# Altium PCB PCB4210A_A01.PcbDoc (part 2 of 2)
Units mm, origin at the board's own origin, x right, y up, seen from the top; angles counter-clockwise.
Board outline 30 x 45 mm, 4 copper layers (Top Layer, Signal Layer 2, Signal Layer 3, Bottom Layer), stack 1.6 mm thick; 78 components, 78 nets, 297 pads, 463 vias.
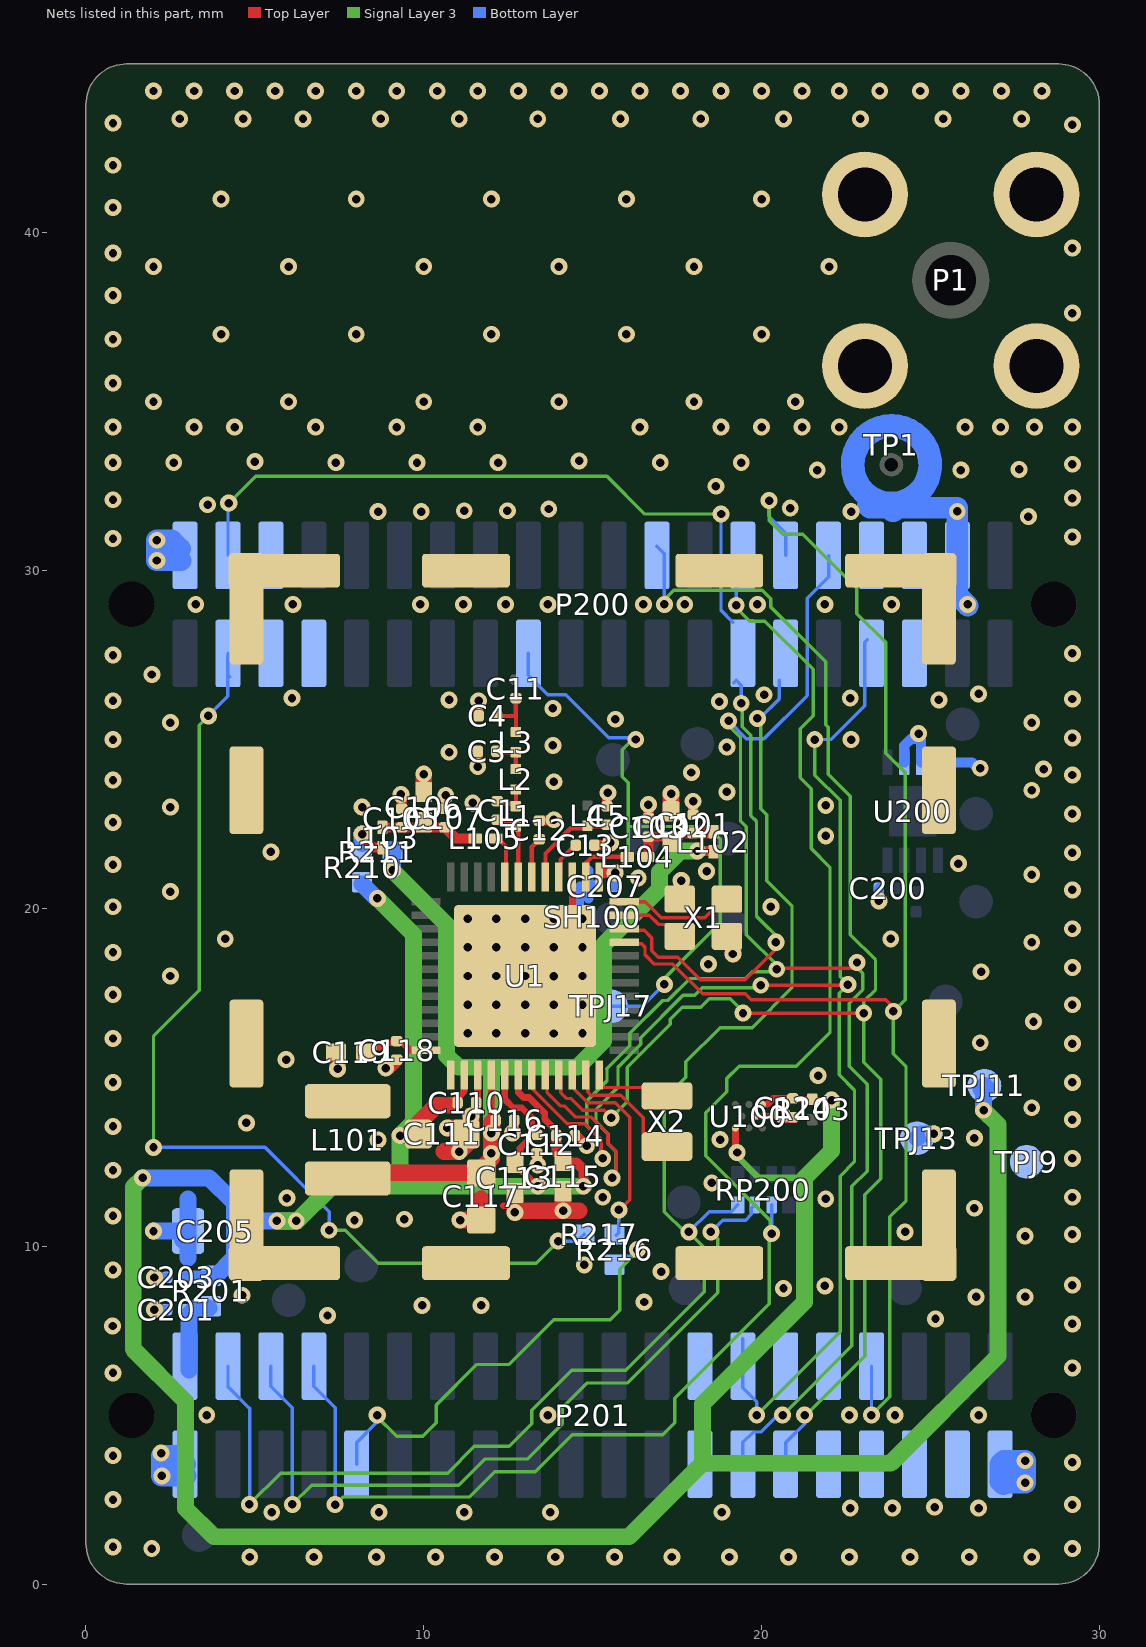
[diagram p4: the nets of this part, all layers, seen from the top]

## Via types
v1: diameter 0.5, hole 0.25, Top Layer to Bottom Layer, tented both sides, 383 vias
v2: diameter 0.508, hole 0.25, Top Layer to Bottom Layer, tented both sides, 80 vias

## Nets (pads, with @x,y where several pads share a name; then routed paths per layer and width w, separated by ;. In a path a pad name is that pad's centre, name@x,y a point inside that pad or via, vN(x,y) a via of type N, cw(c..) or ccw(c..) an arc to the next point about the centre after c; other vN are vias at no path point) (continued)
EFR32_PC8: P200.30 P201.34 U1.9 | length 42.1
  Top Layer w0.1: U1.9@15.935,19 15.985,18.95 16.45,18.95 16.55,18.85 16.55,18.633 16.828,18.355 17.376,18.355 18.255,17.476 19.524,17.476 19.7,17.3 23.677,17.3 23.901,17.076 v2(23.901,16.951)
  Signal Layer 3 w0.1: v2(20.225,32.075) 20.225,31.475 20.625,31.075 21.225,31.075 22.822,29.478 22.822,28.728 23.675,27.875 23.675,24.6 24.25,24.025 24.25,17.3 v2(23.901,16.951) 23.901,15.699 24.274,15.326 24.277,11.352 23.8,10.875 23.8,5.55 v2(23.25,5)
  Bottom Layer w0.1: v2(20.225,32.075) 20.225,31.6 20.715,31.11 P200.30@20.715,30.45 ; v2@23.25,5.05 23.255,5.055 P201.34@23.255,6.45
EFR32_PC9: P200.4 P200.27 U1.10 | length 35.2
  Top Layer w0.1: U1.10@15.935,19.4 15.985,19.35 16.525,19.35 16.75,19.125 16.75,18.75 16.945,18.555 17.52,18.555 18.186,17.889 19.514,17.889 v2@20.488,18.862
  Signal Layer 3 w0.1: v2(4.225,32.002) 4.248,32.002 4.238,32.012 5.025,32.8 15.425,32.8 16.548,31.677 v1(18.801,31.677) ; v2@20.626,18.999 19.85,19.775 19.85,22.575 19.675,22.75 19.675,25.125 19.425,25.375 ; 19.425,25.375 19.425,26.05 19.425,25.375
  Bottom Layer w0.1: P200.4@4.205,30.45 4.205,31.93 v2@4.25,31.975 ; v1(18.801,31.677) 18.724,31.6 18.8,31.524 18.8,28.825 P200.27@19.15,28.475 ; P200.27@19.175,26.675 19.25,26.75 19.4,26.6 v1(19.4,26.075)
  other v2: 20.425,19
EFR32_PD0: U1.48 X2.1 | length 2
  Top Layer w0.1: U1.48@15.2,14.725 15.225,14.7 17.075,14.7 X2.1@17.15,14.775
EFR32_PD1: U1.47 X2.2 | length 3.7
  Top Layer w0.1: U1.47@14.8,15.065 14.85,15.015 14.85,14.575 14.95,14.475 15.825,14.475 16.5,13.8 16.5,13.275 X2.2@17.15,13.275
EFR32_PD2: R216.1 R217.1 U1.46 | length 6.1
  Top Layer w0.1: U1.46@14.4,15.065 14.4,14.708 14.858,14.25 15.675,14.25 16.1,13.825 16.1,11.375 v1@15.8,11.075
  Signal Layer 3 w0.1: v1@15.775,11.1 v1@15.8,11.075
  Bottom Layer w0.1: R216.1@15.7,10.325 15.775,10.4 v1(15.775,11.075)
EFR32_PD3: P200.24 P201.29 U1.45 | length 46.4
  Top Layer w0.1: U1.45@14,15.065 14.05,15.015 14.05,14.55 14.225,14.375 14.35,14.375 14.7,14.025 15.35,14.025 15.55,13.825 v1(15.55,13.8) ; v1(19.45,16.9) 19.45,17.002 19.501,16.951 19.526,16.926 19.576,16.976 19.627,16.925 19.652,16.9 v1(23.025,16.9)
  Signal Layer 3 w0.1: v1(15.55,13.8) 16.025,14.275 16.025,15.292 17.3,16.567 17.3,16.725 17.65,17.075 18.2,17.075 18.45,17.325 19.075,17.325 19.45,16.95 v1(19.45,16.9) ; v1(17.125,29) 16.975,29 17.4,29.425 20.017,29.425 20.276,29.166 20.276,28.924 21.9,27.3 21.9,25.442 21.975,25.367 21.975,23.975 22.625,23.325 22.625,19.225 23.375,18.475 23.375,17.6 23.025,17.25 v1(23.025,16.9) 23.025,15.45 23.525,14.95 23.525,12 23.05,11.525 23.05,6.742 21.308,5 v1(21.275,5)
  Bottom Layer w0.1: P200.24@16.9,30.725 17.125,30.5 v1(17.125,29) ; P201.29@20.715,3.55 20.715,4.19 21.275,4.75 v1(21.275,5)
EFR32_PD4: P200.33 P201.28 U1.44 | length 44.3
  Top Layer w0.1: U1.44@13.6,15.065 13.65,15.015 13.65,14.55 14.05,14.15 14.175,14.15 14.5,13.825 14.953,13.825 15.45,13.328 15.45,13.05 15.701,12.799 15.701,12.151 v1(15.575,12.025) ; v1(19.977,17.725) 22.534,17.725 v1(22.555,17.746)
  Signal Layer 3 w0.1: v1(15.575,12.025) 15.7,12.15 15.7,12.8 15.45,13.05 15.45,13.328 15.1,13.678 15.1,14.05 15.75,14.7 15.75,15.3 16.425,15.975 16.425,16.175 17.675,17.425 18.025,17.425 18.25,17.65 19.902,17.65 v1(19.977,17.725) ; v1(19.859,5) 22.325,7.466 22.325,12.075 22.75,12.5 22.75,14.625 22.3,15.075 22.3,17.491 v1(22.555,17.746) 22.325,17.976 22.325,23.2 21.575,23.95 v1(21.575,25)
  Bottom Layer w0.1: P201.28@19.445,7.263 P201.28@19.445,6.45 19.445,5.805 19.859,5.391 v1(19.859,5) ; v1(21.575,25) 22.05,25 23.05,26 23.05,27.875 P200.33@23.125,27.95
EFR32_PD5: P200.32 P201.27 U1.43 | length 47.9
  Top Layer w0.1: U1.43@13.2,15.065 13.2,14.675 14.25,13.625 14.77,13.625 15.25,13.145 v1@15.25,12.601 ; v1@20.326,18.226 22.651,18.226 v1(22.825,18.4)
  Signal Layer 3 w0.1: v1(15.3,12.601) 15.25,12.651 15.25,13.145 14.825,13.57 14.825,14.3 15.425,14.9 15.425,15.25 ; 15.421,15.254 16.1,15.933 16.1,16.3 17.075,17.275 17.221,17.275 17.871,17.925 19.525,17.925 19.725,18.125 v1@20.375,18.125 ; v1@19.05,25.4 19.375,25.075 19.375,22.6 19.55,22.425 19.55,19.225 v1@20.475,18.3 ; v1(20.625,5) 22.675,7.05 22.675,11.775 23.125,12.225 23.125,14.8 22.6,15.325 22.6,17.2 23,17.6 23,18.075 22.825,18.25 v1(22.825,18.4)
  Bottom Layer w0.1: v1(19.024,25.55) 19.549,25.025 20.072,25.025 21.35,26.303 21.35,29.18 21.985,29.815 P200.32@21.985,30.45 ; P201.27@19.445,3.55 19.445,4.195 19.75,4.5 19.975,4.5 20.475,5 v1(20.625,5)
  other v1: 20.451,18.201
EFR32_RESET: C207.1 P200.17 TPJ17.1 U1.13 | length 19.9
  Top Layer w0.1: U1.13@15.2,20.935 U1.13@15.2,21.075
  Top Layer w0.3: U1.13@15.25,21.05 15.257,21.057 v2(15.664,21.057)
  Signal Layer 3 w0.1: v2(15.664,21.057) 15.664,21.064 16.05,21.45 16.05,22.425 ; v1@16.275,25.1 15.875,24.7 15.875,23.9 16.05,23.725 16.05,22.425 ; v1(16.276,25.001) v1@16.276,25.099 ; v2(17.126,17.751) 17.126,17.926 18.779,19.579 18.779,22.046 18.4,22.425 16.05,22.425
  Bottom Layer w0.1: P200.17@13.095,27.55 13.095,26.905 13.675,26.325 14.2,26.325 15.475,25.05 16.227,25.05 v1(16.276,25.001) ; TPJ17.1@15.55,17.1 16.475,17.1 v2(17.126,17.751)
  Bottom Layer w0.3: v2@15.625,21.075 15.65,21.05 C207.1@15.65,20.65
GND: C3.2 C4.2 C5.2 C12.2 C13.2 C101.2 C102.2 C103.2 C105.2 C106.2 C107.2 C110.2 C111.2 C112.2 C113.2 C114.2 C115.2 C116.2 C117.2 C118.2 C119.2 C124.2 C200.2 C201.2 C203.2 C205.2 C207.2 P1.2 P1.3 P1.4 P1.5 P200.2 P200.38 P201.1 P201.39 SH100.1 TP1.2 TPJ13.1 U1.0 U1.15 U1.39 U100.B2 U200.2 U200.3 U200.4 X1.2 X1.4 | length 43.3
  Top Layer w0.2: v1@2.2,3.8 v1@2.225,3.825 ; U1.0@11.35,16.4 U1.0@11.5,16.25 ; C110.2@11.6,14.3 U1.39@11.6,15.065 ; 12.35,11.199 12.501,11.199 v1(12.7,11) ; U1.15@14.4,20.935 14.4,19.825 U1.0@14.5,19.725 ; U100.B2@19.825,13.85 20.425,13.85 v1@20.45,13.825
  Top Layer w0.3: v1@8.975,15.225 C118.2@9.2,15.45 ; C105.2@9.35,22.95 9.35,23.3 v1@9.375,23.325 ; C107.2@10.6,22.95 10.625,22.975 v1@10.625,23.375 ; v1(11.401,13.851) 11.416,13.851 11.4,13.867 11.55,14.017 C110.2@11.55,14.275 ; v1@11.575,24.225 11.6,24.25 C3.2@11.6,24.65 ; C4.2@11.625,25.7 v1@11.625,26.175 ; v1@12.625,13.4 12.675,13.45 C116.2@12.675,13.725 ; C112.2@13.35,12.75 13.35,12.425 v1(13.375,12.4) ; C12.2@13.4,22.6 v1@13.85,22.6 ; C114.2@14.475,13.275 14.495,13.295 14.505,13.295 v1(14.824,12.976) ; C13.2@15.05,21.875 15.45,21.875 v1@15.5,21.925 ; C5.2@15.425,23.025 v1@15.425,23.375 ; v1(15.526,21.94) v1@15.571,21.94 ; C103.2@16.65,22.675 v1(16.65,23.075) v1@16.65,23.125 ; C101.2@17.975,22.775 v1@17.975,23.125 ; v1@20.525,13.825 20.55,13.8 C124.2@20.975,13.8
  Top Layer w0.5: C119.2@7.4,15.75 7.45,15.7 v1(7.45,15.25) ; C106.2@10,23.5 10,23.85 v1(10,23.975) ; 10.6,12.8 v1(11.05,12.8) 11.35,13.1 C111.2@11.35,13.2 ; v1(10.7,13.5) 10.95,13.5 11.075,13.375 C111.2@11.05,13.35 ; v1(11.075,10.775) C117.2@11.525,10.775 ; C111.2@11.401,13.176 v1(11.401,13.851) ; C117.2@11.7,10.9 11.7,11.4 ; v1(12.7,11) 12.75,11.05 14.6,11.05 ; v1@12.7,11.05 C113.2@12.7,11.575 ; v1(14.125,11.05) C115.2@14.125,11.6 ; C102.2@17.325,22.85 v1(17.325,23.4) ; X1.2@17.6,20.325 17.65,20.375 17.625,20.4 v2(17.625,20.825) ; X1.4@19.125,19.2 19.175,19.15 19.151,19.126 v2(19.151,18.651)
  Bottom Layer w0.254: v1(0.8,9.3) v1@0.875,9.3 ; v1@1.95,8.125 v1(2.025,8.125) ; v1@1.975,9.075 v1(2.025,9.075) C203.2@2.4,9.075 ; v1@2,8.125 C201.2@2.4,8.125
  Bottom Layer w0.3: v1(2.025,8.125) 2,8.125 C201.2@2.4,8.125 ; v1(2.025,9.075) C203.2@2.4,9.075 ; v1@14.6,19.6 14.6,20.625 14.625,20.65 14.875,20.65 ; 14.875,20.3 14.875,20.65 ; 14.875,21.125 14.875,20.65 ; C207.2@15.1,20.65 14.875,20.65 ; v1@23.4,20.15 v1(23.475,20.225) v1@23.475,20.35 ; v1@23.475,20.4 C200.2@23.475,20.6 ; U200.2@24.225,24.325 24.225,24.825 24.413,25.013 24.688,25.013 24.725,24.975 U200.3@24.725,24.325 ; U200.4@25.225,24.325 26.225,24.325 v1@26.425,24.125
  Bottom Layer w0.5: v1(2,10.45) 2.9,10.45 3,10.35 2.85,10.2 C205.2@2.975,10.075 ; 3.025,9.65 C205.2@3.025,10.45 3.025,11.4 ; P200.38@25.795,30.45 P200.38@25.8,30.455
  Bottom Layer w0.508: TPJ13.1@24.6,13.2 24.725,13.325 v1(25.1,13.325)
  Bottom Layer w0.635: P200.2@2.785,30.65 2.535,30.9 v1(2.1,30.9) v1(2.1,30.3) P200.2@2.8,30.3 ; P201.1@2.9,3.25 2.95,3.2 v1(2.25,3.2) 2.25,3.8 2.685,3.8 P201.1@2.935,3.55 ; 23.15,31.925 23.207,31.868 23.867,31.868 23.867,31.755 23.913,31.755 24.025,31.868 25.795,31.868 v1(25.795,31.755) P200.38@25.795,30.45 25.795,29.274 v1@26.101,28.968 ; P201.39@27.065,3.55 27.7,3.55 v1(27.8,3.65) ; P201.39@27.065,3.55 27.065,3.035 27.15,2.95 27.2,3 v1(27.8,3) v1(27.8,3.65) ; P201.39@27.065,3.55 27.165,3.65 v1(27.8,3.65)
  other v1: 4.848,0.8 6.748,0.8 8.598,0.8 10.348,0.8 12.098,0.8 13.898,0.8 15.648,0.8 17.348,0.8 19.048,0.8 20.798,0.8 22.598,0.8 24.398,0.8 26.148,0.8 27.998,0.8 1.948,1.05 29.2,1.05 0.8,1.1 5.5,2.125 8.675,2.125 11.2,2.125 13.75,2.125 18.825,2.125 22.625,2.25 23.875,2.25 26.425,2.25 25.125,2.275 29.2,2.35 0.8,2.5 29.2,3.6 0.8,3.8 2.225,3.875 3.575,5 13.675,5 22.6,5 23.95,5 26.425,5 0.8,6.25 29.2,6.4 0.786,7.638 29.2,7.7 25.15,7.85 7.15,7.95 9.95,8.25 11.7,8.25 16.525,8.35 26.35,8.5 27.8,8.5 4.625,8.55 20.65,8.75 21.875,8.825 29.2,8.85 17.026,9.25 14.75,9.45 27.8,10.3 29.2,10.35 24.25,10.425 7.95,10.775 9.425,10.8 0.8,10.9 26.3,11.125 21.9,11.4 5.95,11.425 15.3,11.45 29.2,11.45 18.525,11.875 0.8,12.25 29.2,12.6 8.65,13.15 18.775,13.159 26.3,13.2 12.625,13.35 0.8,13.55 4.75,13.65 29.2,13.75 20.6,13.9 28,14.1 0.8,14.85 29.2,14.85 21.675,15.05 8.875,15.276 5.925,15.525 29.2,16 26.475,16.025 0.8,16.15 11.3,16.3 12.15,16.3 13,16.3 13.85,16.298 14.7,16.3 28.05,16.65 11.3,17.15 12.15,17.15 13,17.15 13.85,17.148 14.7,17.15 29.2,17.15 0.8,17.45 2.5,18 11.3,18 12.15,18 13,18 13.85,17.998 14.7,18 26.5,18.125 29.2,18.25 18.425,18.35 0.8,18.7 11.3,18.85 12.15,18.85 13,18.85 13.85,18.848 14.7,18.85 28,19 4.125,19.1 23.825,19.1 29.2,19.4 11.3,19.7 12.15,19.7 13,19.7 13.85,19.698 14.7,19.7 0.8,20.05 2.5,20.5 29.2,20.55 16.35,20.9 28,21 0.8,21.3 25.825,21.325 29.2,21.65 5.475,21.675 21.9,22.15 0.8,22.55 13.85,22.625 29.2,22.8 2.5,23 8.175,23 21.9,23.05 11.45,23.125 17.975,23.175 10.65,23.35 9.325,23.375 15.45,23.425 18.975,23.45 28,23.5 13.85,23.75 0.8,23.8 29.2,23.95 17.925,24.025 28.35,24.125 26.475,24.15 11.6,24.2 10.75,24.625 18.975,24.775 13.825,24.825 0.8,25 22.65,25 29.2,25.05 24.65,25.175 2.5,25.5 28,25.5 15.675,25.6 13.825,25.925 18.75,26.125 0.8,26.15 11.625,26.15 10.75,26.175 25.25,26.175 29.2,26.2 6.1,26.225 22.625,26.225 20.075,26.325 26.425,26.35 1.95,26.925 0.8,27.5 29.2,27.55 3.25,29 6.125,29 9.9,29 11.175,29 12.425,29 13.675,29 16.5,29 17.725,29 19.876,29 21.876,29 23.85,29 26.101,29 0.8,30.95 29.2,31 27.9,31.6 8.65,31.75 9.925,31.75 22.65,31.75 11.2,31.775 12.475,31.775 13.7,31.825 20.85,31.85 3.6,31.95 0.8,32.1 29.2,32.15 18.65,32.5 21.65,32.975 25.9,32.975 27.625,33 29.2,33.15 0.8,33.2 2.6,33.2 7.4,33.2 9.8,33.2 12.2,33.2 17,33.2 19.4,33.2 5,33.227 14.601,33.252 0.8,34.25 3.2,34.25 4.4,34.25 6.8,34.25 9.2,34.25 11.6,34.25 16.4,34.25 18.8,34.25 20,34.25 21.2,34.25 22.3,34.25 26.025,34.25 27.075,34.25 28.075,34.25 29.2,34.25 2,35 6,35 10,35 14,35 18,35 21,35 0.8,35.55 0.8,36.85 4,37 8,37 12,37 16,37 20,37 29.2,37.625 0.8,38.15 2,39 6,39 10,39 14,39 18,39 22,39 0.8,39.4 29.2,39.55 0.8,40.75 4,41 8,41 12,41 16,41 20,41 0.8,42 29.2,43.2 0.8,43.25 2.775,43.375 4.65,43.375 6.425,43.375 8.725,43.375 11.05,43.375 13.375,43.375 15.825,43.375 18.2,43.375 20.65,43.375 22.925,43.375 25.375,43.375 27.7,43.375 2,44.2 3.2,44.2 4.4,44.2 5.6,44.2 6.8,44.2 8,44.2 9.2,44.2 10.4,44.2 11.6,44.2 12.8,44.2 14,44.2 15.2,44.2 16.4,44.2 17.6,44.2 18.8,44.2 20,44.2 21.2,44.2 22.3,44.2 23.5,44.2 24.7,44.2 25.9,44.2 27.1,44.2 28.3,44.2
  other v2: 20.275,20.05 18.375,21.1
N17556303: C101.1 C102.1 C103.1 L102.2 L104.1 | length 2.5
  Top Layer w0.3: L104.1@16.65,21.6 C103.1@16.65,22.125 17.55,22.125 17.65,22.225 C101.1@17.975,22.225 L102.2@18.55,22.225
N17556352: C1.1 L1.1 U1.19 | length 2.1
  Top Layer w0.1: C1.1@12.25,22.625 12.25,22.55 12.225,22.525 12.6,22.525 L1.1@12.675,22.45
  Top Layer w0.125: U1.19@12.8,20.95 L1.1@12.8,22.425
N17556358: C1.2 L1.2 L2.1 | length 1
  Top Layer w0.125: C1.2@12.225,23.1 12.65,23.1 L1.2@12.725,23.025 ; L1.2@12.73,22.987 L2.1@12.73,23.458
N17556449: L104.2 U1.14 | length 1.7
  Top Layer w0.125: U1.14@14.8,20.935 14.8,21.35 14.977,21.527 15.973,21.527 15.975,21.525 L104.2@16.025,21.525 L104.2@16.05,21.525
N17556453: L105.2 U1.20 | length 1.2
  Top Layer w0.125: L105.2@12.261,22.014 12.438,21.837 U1.20@12.438,20.988 ; U1.20@12.4,20.95 U1.20@12.45,21
N17556723: C118.1 C119.1 U1.36 | length 1.7
  Top Layer w0.2: C119.1@8.475,15.9 8.775,15.9 8.9,16.025 9.375,16.025 9.6,15.8 U1.36@10.065,15.8 U1.36@10.075,15.8
N17556727: L101.1 U1.37
N17556799: C5.1 L4.1 U1.17 | length 2.8
  Top Layer w0.125: U1.17@13.6,20.95 13.6,21.625 14.35,22.375 14.875,22.375 14.875,22.425 15.3,22.425 C5.1@15.35,22.475 ; L4.1@14.847,22.445 L4.1@14.85,22.45 L4.1@14.86,22.463
N17556841: C3.1 L2.2 L3.1 | length 1.2
  Top Layer w0.125: C3.1@12.125,24.625 L3.1@12.725,24.625 ; L2.2@12.725,24.05 L3.1@12.725,24.625 ; L3.1@12.725,24.575 L3.1@12.725,24.625
N17556911: C4.1 C11.1 L3.2 | length 2.2
  Top Layer w0.125: C4.1@12.179,25.654 12.225,25.7 12.725,25.7 12.725,26.233 C11.1@12.73,26.238 ; L3.2@12.73,25.145 C11.1@12.73,26.225
N17557012: C13.1 U1.16 | length 1.1
  Top Layer w0.125: U1.16@14,20.95 14.05,21 14.05,21.45 14.4,21.8 C13.1@14.5,21.8
N17557016: C12.1 U1.18 | length 1.1
  Top Layer w0.125: U1.18@13.2,20.95 13.2,21.825 C12.1@13.35,21.975
N17557090: C105.1 C106.1 C107.1 L103.2 L105.1 | length 3
  Top Layer w0.3: L103.2@8.775,22.4 C105.1@9.35,22.4 9.85,22.4 C106.1@10,22.55 10.15,22.4 C107.1@10.625,22.4 10.95,22.075 L105.1@11.5,22.075
N17557115: U1.11 X1.3 | length 1.9
  Top Layer w0.1: U1.11@15.935,19.8 16.675,19.8 16.95,19.525 17.192,19.525 17.225,19.525 X1.3@17.575,19.175
N17557130: U1.12 X1.1 | length 3.5
  Top Layer w0.1: U1.12@15.935,20.2 16.558,20.2 17.033,19.725 18.325,19.725 18.875,20.275 X1.1@18.975,20.275
PAVDD: L103.1 R210.1 R211.2 | length 1.1
  Top Layer w0.3: v1(8.175,22.2) 8.15,22.2 8.125,22.175 8.5,21.8 L103.1@8.775,21.8
  Bottom Layer w0.5: R211.2@8.175,21.925 v1(8.175,22.2)
USB_VBUS: P200.35
USB_VREG: P200.36
VDCDC: C116.1 C117.1 L101.2 L102.1 R211.1 U1.40 | length 29.9
  Top Layer w0.2: C116.1@12,13.85 12,14.55 U1.40@12,14.955
  Top Layer w0.3: v1(18.1,21.7) 18.5,21.7 L102.1@18.575,21.625
  Top Layer w0.5: L101.2@8.625,12.175 C117.1@11.55,12.175 ; C117.1@11.575,12.175 12,12.6 v1(12,12.75) ; v1@12.001,12.849 v1(12.001,13.351) 12.025,13.375 C116.1@12.025,13.685
  Signal Layer 3 w0.5: v2(9.075,21.125) 10.675,19.525 10.675,15.65 11.025,15.3 12.001,15.3 ; v1(12,12.75) v1@12,13.301 ; v1(12.001,13.351) 12.001,15.3 ; v1(18.1,21.7) 17.6,21.7 16.975,21.075 16.975,20.575 ; 12.001,15.3 14.549,15.3 15.325,16.076 15.325,18.925 ; 15.325,18.925 16.975,20.575 ; 15.325,18.925 16.975,20.575
  Bottom Layer w0.5: v2(9.075,21.125) 9.075,21.699 R211.1@9.1,21.725
VMCU: C110.1 C111.1 C112.1 C113.1 C114.1 C115.1 C124.1 C203.1 C205.1 R103.2 R201.2 R210.2 TPJ11.1 U1.38 U1.41 U1.42 U100.A1 U100.E3 | length 103.8
  Top Layer w0.2: 10.625,14.025 10.775,14.025 C110.1@11,14.25 ; C110.1@10.9,14.25 10.9,14.275 10.9,14.3 11.2,14.6 U1.38@11.2,15.065 ; U1.41@12.4,15.08 U1.41@12.4,15.065 ; C113.1@12.65,12.575 12.85,12.575 12.85,12.9 13.2,13.25 13.2,13.8 12.9,14.1 12.65,14.1 12.4,14.35 12.4,14.575 ; C113.1@12.7,12.475 12.7,12.439 13.289,11.85 v1@13.375,11.85 ; U1.42@12.8,15 12.8,14.55 12.95,14.4 13.121,14.4 13.579,13.942 13.579,13.761 13.939,13.401 C114.1@13.95,13.39 ; v1@19.225,12.924 U100.E3@19.225,13.5 ; U100.A1@20.025,14.225 U100.A1@20.025,14.2 20.167,14.2 20.342,14.375 20.64,14.375 20.761,14.375 20.79,14.346 20.896,14.346 C124.1@20.925,14.375 C124.1@20.95,14.35 ; C124.1@21,14.35 R103.2@21.475,14.35 ; R103.2@21.5,14.35 21.55,14.4 21.625,14.325 v2(22.075,14.325) ; 12.4,14.575 U1.41@12.4,15.065 ; 12.4,14.575 U1.41@12.4,15.065
  Top Layer w0.3: 10.525,14.175 10.625,14.275 10.9,14.275 C110.1@11,14.275 ; C114.1@13.925,13.225 13.925,12.775 C115.1@14.125,12.575 ; C115.1@14.025,12.65 C115.1@14.05,12.625 ; C115.1@14.25,12.475 14.525,12.475 14.725,12.275 v1(14.725,11.775)
  Top Layer w0.5: v1(9.3,13.275) C111.1@9.825,13.275 ; C111.1@9.85,13.175 C111.1@9.825,13.175 ; 10.65,14.175 10.525,14.175 10.375,14.175 9.825,13.625 C111.1@9.825,13.275 ; C111.1@9.825,13.175 9.925,13.275 C111.1@9.825,13.275 ; C111.1@9.825,13.175 C111.1@9.825,13.275
  Signal Layer 3 w0.2: v1(19.276,12.776) 19.276,12.719 19.25,12.693 19.918,12.025 21.275,12.025
  Signal Layer 3 w0.5: v2(1.675,12.025) 1.4,11.75 1.4,6.95 2.95,5.4 2.95,2.24 3.79,1.4 16.075,1.4 18.25,3.575 ; v1(5.65,10.75) v1(6.225,10.75) 6.25,10.75 7.275,11.775 9.3,11.775 ; v2(8.628,20.297) 9.7,19.225 9.7,13.675 v1(9.3,13.275) 9.3,11.775 ; v1(14.725,11.775) v1(13.375,11.775) 9.3,11.775 ; v2(22.075,14.325) 22.075,12.825 21.275,12.025 21.275,8.35 18.25,5.325 18.25,3.575 ; v1(26.575,14.025) 27,13.6 27,6.75 23.825,3.575 18.25,3.575
  Bottom Layer w0.4: C203.1@3,9.075 R201.2@3.8,9.075
  Bottom Layer w0.5: v2(1.675,12.025) 3.65,12.025 4.4,11.275 C205.1@4.4,10.35 ; R201.2@3.775,9.1 3.8,9.075 4.4,9.675 C205.1@4.4,10.35 ; C205.1@4.55,10.75 v1(5.65,10.75) v1(6.225,10.75) ; C205.1@4.625,10.35 C205.1@4.4,10.35 ; R210.2@8.175,20.725 8.603,20.297 v2(8.628,20.297)
  Bottom Layer w0.508: v1(26.575,14.025) 26.575,14.575 TPJ11.1@26.5,14.65 ; TPJ11.1@26.6,14.75 TPJ11.1@26.55,14.7 ; TPJ11.1@26.65,14.7 26.6,14.65 TPJ11.1@26.55,14.7 ; TPJ11.1@26.5,14.65 TPJ11.1@26.55,14.7 ; TPJ11.1@26.5,14.65 TPJ11.1@26.55,14.7
  Bottom Layer w0.75: C205.1@4.625,10.35 4.725,10.45 C205.1@4.625,10.45
VMCU_IN: C201.1 P201.2 R201.1 | length 2.3
  Bottom Layer w0.5: P201.2@3.05,6.335 3.05,8 3.225,8.175 R201.1@3.65,8.175
VRF: TPJ9.1
WSTK_F15: P200.28 P201.8 RP200.6 | length 48.5
  Signal Layer 3 w0.1: v2(7.375,2.35) 7.6,2.575 11.35,2.575 12.1,3.325 13.3,3.325 14.4,4.425 17.075,4.425 17.425,4.775 17.425,5.5 20.225,8.3 20.225,10.3 v1(20.3,10.375) 20.4,10.375 20.4,10.425 20.25,10.575 20.25,10.775 18.35,12.675 18.35,13.95 18.975,14.575 18.975,14.966 19.343,15.334 21.034,15.334 22.025,16.325 22.025,21.225 21.475,21.775 21.475,23.55 21.15,23.875 21.15,25.325 21.525,25.7 21.525,27.075 20.1,28.5 19.65,28.5 19.238,28.913 19.25,28.925 v1(19.25,28.975) 19.225,28.975 v1@19.15,29.05
  Bottom Layer w0.1: P201.8@6.745,6.45 6.745,5.855 7.375,5.225 v2(7.375,2.35) ; v1(19.25,28.975) 19.175,28.975 19.25,29.05 19.25,30.255 P200.28@19.445,30.45 ; v1@20.3,10.55 RP200.6@20.3,11.225
WSTK_F16: P200.29 P201.4 RP200.8 | length 43.8
  Signal Layer 3 w0.1: v2(4.84,2.358) 5.767,3.285 10.71,3.285 11.5,4.075 12.525,4.075 13.2,4.75 13.2,5.15 14.375,6.325 15.975,6.325 18.3,8.65 18.3,9.95 17.824,10.426 17.724,10.426 17.125,11.025 17.125,14.375 17.758,15.008 17.758,15.458 18.771,16.471 19.721,16.471 20.9,17.65 20.9,20.075 20.15,20.825 20.15,22.775 19.975,22.95 v1@19.975,25.525
  Bottom Layer w0.1: P201.4@4.205,6.45 4.205,5.835 4.84,5.2 4.85,5.2 4.85,2.368 v2(4.84,2.358) ; v2(17.851,10.426) 18.45,11.025 19.1,11.025 RP200.8@19.3,11.225 ; v1(19.875,25.625) 19.95,25.625 20.525,26.2 P200.29@20.525,26.75
WSTK_F21: P200.34
WSTK_P3: P201.6 RP200.7 | length 23.7
  Signal Layer 3 w0.1: v2@6.11,2.56 v2(6.11,2.358) 6.682,2.93 11.03,2.93 11.8,3.7 13.063,3.7 14.1,4.737 14.1,5.225 14.825,5.95 16.025,5.95 18.7,8.625 18.7,10.225 v2(18.5,10.425)
  Bottom Layer w0.1: P201.6@5.475,6.45 5.475,5.85 6.11,5.215 v2(6.11,2.358) ; v2(18.5,10.425) 18.85,10.775 19.534,10.775 19.7,10.941 19.7,11.125 RP200.7@19.8,11.225
WSTK_P6: P201.9 R216.2 | length 13.9
  Signal Layer 3 w0.1: v2@8.6,5.15 8.6,4.975 9.2,4.375 9.975,4.375 10.375,4.775 10.375,5.3 11.575,6.5 12.525,6.5 13.85,7.825 15.525,7.825 15.8,8.1 15.8,9.325 v1@16.4,9.925 ; v1@16.4,9.85 v1@16.475,9.85
  Bottom Layer w0.1: P201.9@8.015,3.55 8.015,4.19 8.625,4.8 v2(8.625,5) ; R216.2@15.9,9.7 16.2,9.7 16.326,9.826 v1(16.326,9.9)
WSTK_P22: P201.25
WSTK_P23: P201.26
WSTK_P27: P201.30
WSTK_P28: P201.31
WSTK_P29: P201.32
WSTK_P30: P201.33
WSTK_P32: P201.35
WSTK_P34: P201.37
WSTK_P36: P200.3 R217.2 | length 31.3
  Signal Layer 3 w0.1: v1(2,12.925) 2,16.225 3.35,17.575 3.35,25.425 v2(3.625,25.7) v2@3.75,25.575 ; v1(7.2,10.475) 7.675,10.475 8.65,9.5 13.325,9.5 v1(13.975,10.15) v1@14.05,10.225
  Bottom Layer w0.1: v1(2,12.925) 5.3,12.925 7.2,11.025 v1@7.2,10.5 ; v2(3.625,25.7) 4.2,26.275 P200.3@4.2,27.5 ; P200.3@4.205,27.55 4.205,26.92 P200.3@4.263,26.862 ; v1@14,10.125 14.025,10.15 14.55,10.15 R217.2@14.75,10.35
WSTK_P38: P200.5
WSTK_P39: P200.6
WSTK_P40: P200.7
pads on no net: P200.M1 P200.M2 P201.40 P201.M1 P201.M2 RP200.4 RP200.5 TPJ18.1 TPJ19.1 TPJ20.1 U100.C1 U200.9

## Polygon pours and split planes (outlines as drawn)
GND on Signal Layer 2 "GND_L2" (solid, remove dead copper, pour order 48): 0,0 0,45 30,45 30,0
GND on Bottom Layer "GND_L4" (solid, remove dead copper, pour order 54): 0,0 0,45 30,45 30,0
GND on Top Layer "GND_L1" (solid, remove dead copper, pour order 56): 0,0 0,45 30,45 30,0
GND on Signal Layer 3 "GND_L3" (solid, remove dead copper, pour order 52): 0,0 0,45 30,45 30,0

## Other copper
Top Layer:
  pour cut-out: 17.438,21.225 17.85,21.225 18.25,20.825 19.513,20.825 19.675,20.663 19.675,18.575 19.325,18.225 19,18.225 18.625,18.6 16.75,18.6 16.75,20.537
  region net GND: 13.375,26.2 13.375,23.25 14.075,23.25 14.3,23.475 14.3,26 14.1,26.2
  pour cut-out: 12.875,22.375 15.425,22.375 15.425,27.875 12.875,27.875
  region net N17556727: 7.762,13.8 7.763,14.8 9.05,14.8 9.75,15.5 10.912,15.5 10.912,14.65 9.9,14.65 9.05,13.8
  pour cut-out: 12.6,26.525 11.425,26.525 11,26.1 11,23.713 12.6,23.713
  pour cut-out: 11.175,22.65 11.175,24.375 9.35,24.375 8.5,23.525 8.5,22.65
  pour cut-out: 18.4,22.075 18.4,23.388 18.012,23.775 16.9,23.775 16.65,23.525 16,23.525 15.475,24.05 15.1,24.05 15.1,22.075
Bottom Layer:
  pour cut-out: 19.375,26.838 18.1,26.838 18.1,26.462 19.375,26.462
  pour cut-out: 23.25,26.838 21.975,26.838 21.975,26.462 23.25,26.462
  pour cut-out: 8.05,31.538 6.775,31.538 6.775,31.163 8.05,31.163
  pour cut-out: 5.65,28.637 4.375,28.637 4.375,28.262 5.65,28.262
  pour cut-out: 9.25,26.838 7.975,26.838 7.975,26.462 9.25,26.462
  pour cut-out: 17.175,31.538 14.425,31.538 14.425,31.163 17.175,31.163
  pour cut-out: 20.55,2.837 14.527,2.837 14.527,2.462 20.55,2.462
  pour cut-out: 13.25,2.837 8.177,2.837 8.177,2.462 13.25,2.462
  pour cut-out: 13.175,7.538 4.475,7.538 4.475,7.163 13.175,7.163
  pour cut-out: 20.6,7.538 17.05,7.538 17.05,7.163 20.6,7.163
  pour cut-out: 23.225,30.75 23.225,28.85 23.6,28.85 23.6,30.75
  pour cut-out: 21.1,11.863 19,11.863 19,11.488 21.1,11.488

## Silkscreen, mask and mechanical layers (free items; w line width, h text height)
Top Overlay:
  text "EFR32xG23B" at 0.85,41.4 h3.2
  text "868-915 MHz" at 1,39 h1.9
  text "20 dBm" at 1,37 h1.9
Bottom Overlay:
  lines w0.15: 1.5,38 1.5,37 2.5,37 ; 1.5,42 1.5,43 2.5,43 ; 19.5,37 20.5,37 20.5,38 ; 19.5,43 20.5,43 20.5,42
  lines w0.152: 7.675,20.525 7.675,20.225 7.975,20.225 ; 7.675,21.475 7.675,21.225 7.775,21.225 ; 7.675,21.925 7.675,22.175 7.775,22.175 ; 8.375,20.225 8.675,20.225 8.675,20.525 ; 8.375,22.175 8.675,22.175 ; 8.675,20.875 8.675,21.175 8.975,21.175 ; 9.325,21.175 9.625,21.175 9.625,21.475 ; 9.325,22.175 9.625,22.175 9.625,21.875 ; 14.2,10.175 14.2,9.875 14.5,9.875 ; 14.2,10.575 14.2,10.875 14.5,10.875 ; 14.85,9.875 15.15,9.875 15.15,9.575 ; 15.15,9.225 15.15,8.925 15.45,8.925 ; 15.2,10.775 15.2,10.875 15.45,10.875 ; 15.85,8.925 16.15,8.925 16.15,9.225 ; 15.9,10.875 16.15,10.875 16.15,10.775 ; 16.15,9.875 16.15,10.175
  text "BOARD INFO" at 20.55,43.35 h1.6
  text "PAVDD / Config." at 12.3,22.45 h1.6
  text "VDCDC" at 13.825,21.25 h1.2
  text "VMCU" at 6.6,19.075 h1.2 r270
  text "PCB4210A Rev. A01" at 28,13.7 h1.52 r270
  text "EFR32_PD02 / Config." at 18.8,11.025 h1.6
  text "JOYSTICK" at 13.9,9.975 h1.2
  text "EXP9" at 16.375,8.5 h1.2 r270
Top Solder:
  the board outline again, w0.8
Bottom Solder:
  the board outline again, w0.8
BOARD OUTLINE 1:
  the board outline again, w0.1
Mechanical 11:
  the board outline again, w0.1
Mechanical 12:
  the board outline again, w0.1
Mechanical 15:
  lines w0.025: 69.971,-48.875 70.179,-48.875 ; 70.075,-48.979 70.075,-48.771
  lines w0.1: -0.5,0 0.5,0 ; 0,-0.5 0,0.5
Mechanical 16:
  lines w0.1: -0.5,0 0.5,0 ; 0,-0.5 0,0.5
Mechanical 26:
  lines w0.2: -122.4,-40.25 -120.775,-40.25 ; -122.4,6.425 -120.775,6.425 ; -122.4,53.1 -120.775,53.1 ; -67.75,-88.5 -67.75,-86.9 ; -67.75,99.8 -67.75,101.4 ; -14.725,-88.5 -14.725,-86.9 ; -14.725,99.8 -14.725,101.4 ; 38.3,-88.5 38.3,-86.9 ; 38.3,99.8 38.3,101.4 ; 91.325,-88.5 91.325,-86.9 ; 91.325,99.8 91.325,101.4 ; 144.35,-40.225 145.975,-40.225 ; 144.35,6.45 145.975,6.45 ; 144.35,53.125 145.975,53.125 ; 145.975,-88.5 -122.4,-88.5 -122.4,101.4 145.975,101.4 145.975,-88.475 ; -120.775,-86.9 -120.775,99.8 144.35,99.8 144.35,-86.9 -120.775,-86.9
  text "5" at -94.425,100.325 h0.5
  text "4" at -41.4,100.3 h0.5
  text "3" at 11.625,100.3 h0.5
  text "2" at 64.65,100.3 h0.5
  text "1" at 117.775,100.3 h0.5
  text "D" at 145.025,76.2 h0.5
  text "D" at -121.725,76.175 h0.5
  text "C" at 145.025,29.5 h0.5
  text "C" at -121.725,29.475 h0.5
  text "B" at 145.025,-17.175 h0.5
  text "B" at -121.725,-17.2 h0.5
  text "A" at 145.025,-63.825 h0.5
  text "A" at -121.725,-63.85 h0.5
  text "5" at -94.425,-87.975 h0.5
  text "4" at -41.4,-88 h0.5
  text "3" at 11.625,-88 h0.5
  text "2" at 64.65,-88 h0.5
  text "1" at 117.775,-88 h0.5
Mechanical 27:
  drawing of 28 lines, arcs and shapes, not listed
  text "Board Title" at 74.75,-61.95 h2.5
  text ".BoardTitle" at 76.15,-67.5 h3.5
  text "Page Title" at 74.75,-71.675 h2.5
  text "Designed:" at 42.5,-75.425 h1.7
  text "Approved:" at 58.7,-75.425 h1.7
  text "Top Assembly" at 76.15,-75.575 h3.2
  text "TAB" at 44.025,-77.925 h2.2
  text "RGU" at 60.075,-77.925 h2.2
  text "Revision" at 132.65,-78.7 h1.7
  text "Document number" at 74.75,-78.975 h2.35
  text "Size" at 42.5,-80.175 h1.7
  text "BOM Doc. No:" at 47.425,-80.175 h1.7
  text ".BoardRevision" at 132.925,-81.75 h2.7
  text ".BoardName" at 76.15,-81.85 h3.2
  text "A4" at 43.075,-82.025 h2
  text "<>" at 48,-82.025 h2
  text "Design Created Date:" at 42.5,-84.375 h1.7
  text "Sheet Created Date:" at 74.175,-84.375 h1.7
  text "Sheet Modified Date:" at 102.6,-84.375 h1.7
  text "Sheet" at 132.65,-84.375 h1.7
  text "Monday, July 13, 2020" at 43.575,-86.325 h1.7
  text "Monday, July 13, 2020" at 75.3,-86.325 h1.7
  text "'.Print_Date'" at 103.725,-86.325 h1.7
  text "1" at 133.85,-86.325 h1.7
  text "of" at 136.975,-86.325 h1.7
  text "2" at 139.7,-86.325 h1.7
Mechanical 28:
  lines w0.2: -122.4,-40.25 -120.775,-40.25 ; -122.4,6.425 -120.775,6.425 ; -122.4,53.1 -120.775,53.1 ; -67.75,-88.5 -67.75,-86.9 ; -67.75,99.8 -67.75,101.4 ; -14.725,-88.5 -14.725,-86.9 ; -14.725,99.8 -14.725,101.4 ; 38.3,-88.5 38.3,-86.9 ; 38.3,99.8 38.3,101.4 ; 91.325,-88.5 91.325,-86.9 ; 91.325,99.8 91.325,101.4 ; 144.35,-40.225 145.975,-40.225 ; 144.35,6.45 145.975,6.45 ; 144.35,53.125 145.975,53.125 ; 145.975,-88.5 -122.4,-88.5 -122.4,101.4 145.975,101.4 145.975,-88.475 ; -120.775,-86.9 -120.775,99.8 144.35,99.8 144.35,-86.9 -120.775,-86.9
  text "5" at -94.1,100.325 h0.5
  text "4" at -41.075,100.3 h0.5
  text "3" at 11.95,100.3 h0.5
  text "2" at 64.975,100.3 h0.5
  text "1" at 117.95,100.3 h0.5
  text "D" at 145.35,76.2 h0.5
  text "D" at -121.4,76.175 h0.5
  text "C" at 145.35,29.5 h0.5
  text "C" at -121.4,29.475 h0.5
  text "B" at 145.35,-17.175 h0.5
  text "B" at -121.4,-17.2 h0.5
  text "A" at 145.35,-63.825 h0.5
  text "A" at -121.4,-63.85 h0.5
  text "5" at -94.1,-87.975 h0.5
  text "4" at -41.075,-88 h0.5
  text "3" at 11.95,-88 h0.5
  text "2" at 64.975,-88 h0.5
  text "1" at 117.95,-88 h0.5
Mechanical 29:
  drawing of 28 lines, arcs and shapes, not listed
  text "Board Title" at -51.175,-61.95 h2.5
  text ".BoardTitle" at -52.575,-67.5 h3.5
  text "Page Title" at -51.175,-71.675 h2.5
  text "Approved:" at -35.125,-75.425 h1.7
  text "Designed:" at -18.925,-75.425 h1.7
  text "Bottom Assembly" at -52.575,-75.575 h3.2
  text "RGU" at -36.5,-77.925 h2.2
  text "TAB" at -20.45,-77.925 h2.2
  text "Revision" at -109.075,-78.7 h1.7
  text "Document number" at -51.175,-78.975 h2.35
  text "BOM Doc. No:" at -23.85,-80.175 h1.7
  text "Size" at -18.925,-80.175 h1.7
  text ".BoardRevision" at -109.339,-81.75 h2.7
  text ".BoardName" at -52.575,-81.85 h3.2
  text "<>" at -24.425,-82.025 h2
  text "A4" at -19.5,-82.025 h2
  text "Sheet" at -109.075,-84.375 h1.7
  text "Sheet Modified Date:" at -79.025,-84.375 h1.7
  text "Sheet Created Date:" at -50.6,-84.375 h1.7
  text "Design Created Date:" at -18.925,-84.375 h1.7
  text "2" at -116.125,-86.325 h1.7
  text "of" at -113.4,-86.325 h1.7
  text "2" at -110.275,-86.325 h1.7
  text "'.Print_Date'" at -80.15,-86.325 h1.7
  text "Monday, July 13, 2020" at -51.725,-86.325 h1.7
  text "Monday, July 13, 2020" at -20,-86.325 h1.7
Mechanical 30:
  lines w0.2: -126.75,-94.975 156.75,-94.975 156.75,105.5 -126.75,105.5 -126.75,-94.975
